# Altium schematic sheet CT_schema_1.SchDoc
size 516 x 258 mm
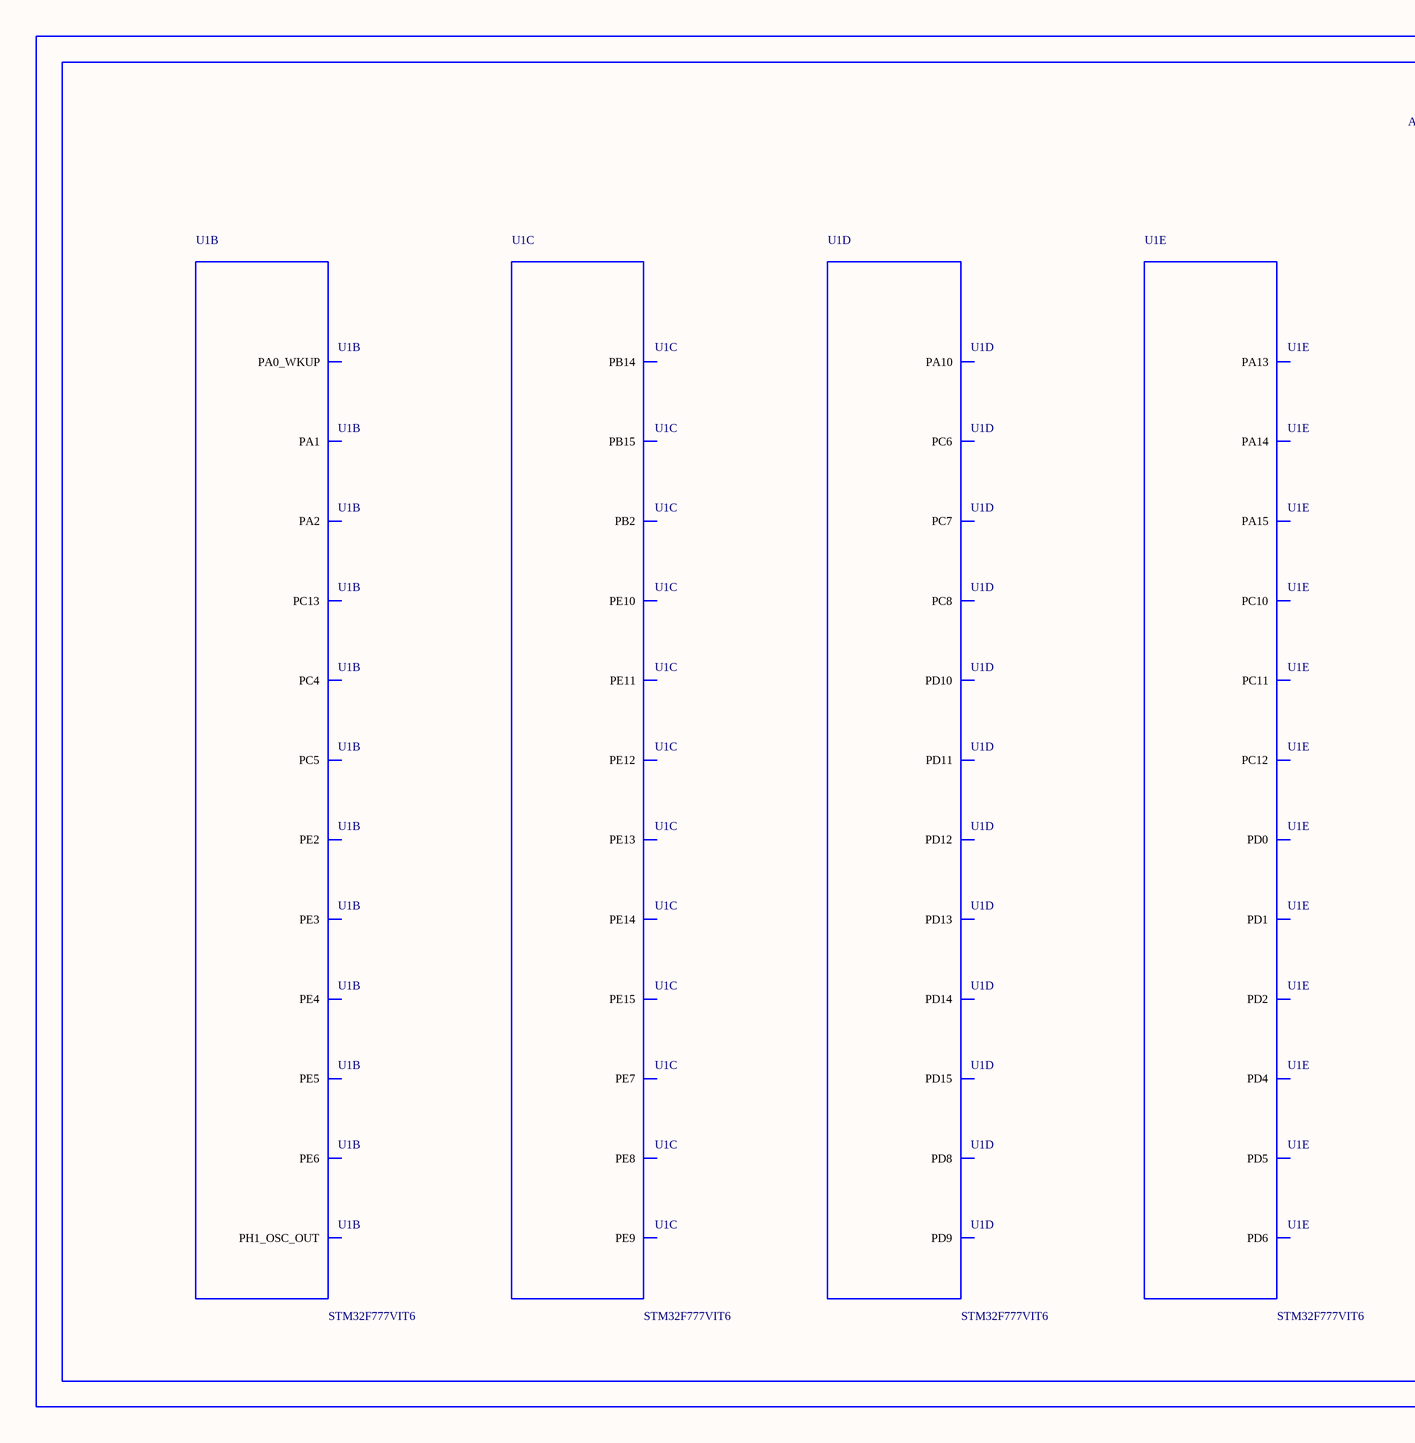
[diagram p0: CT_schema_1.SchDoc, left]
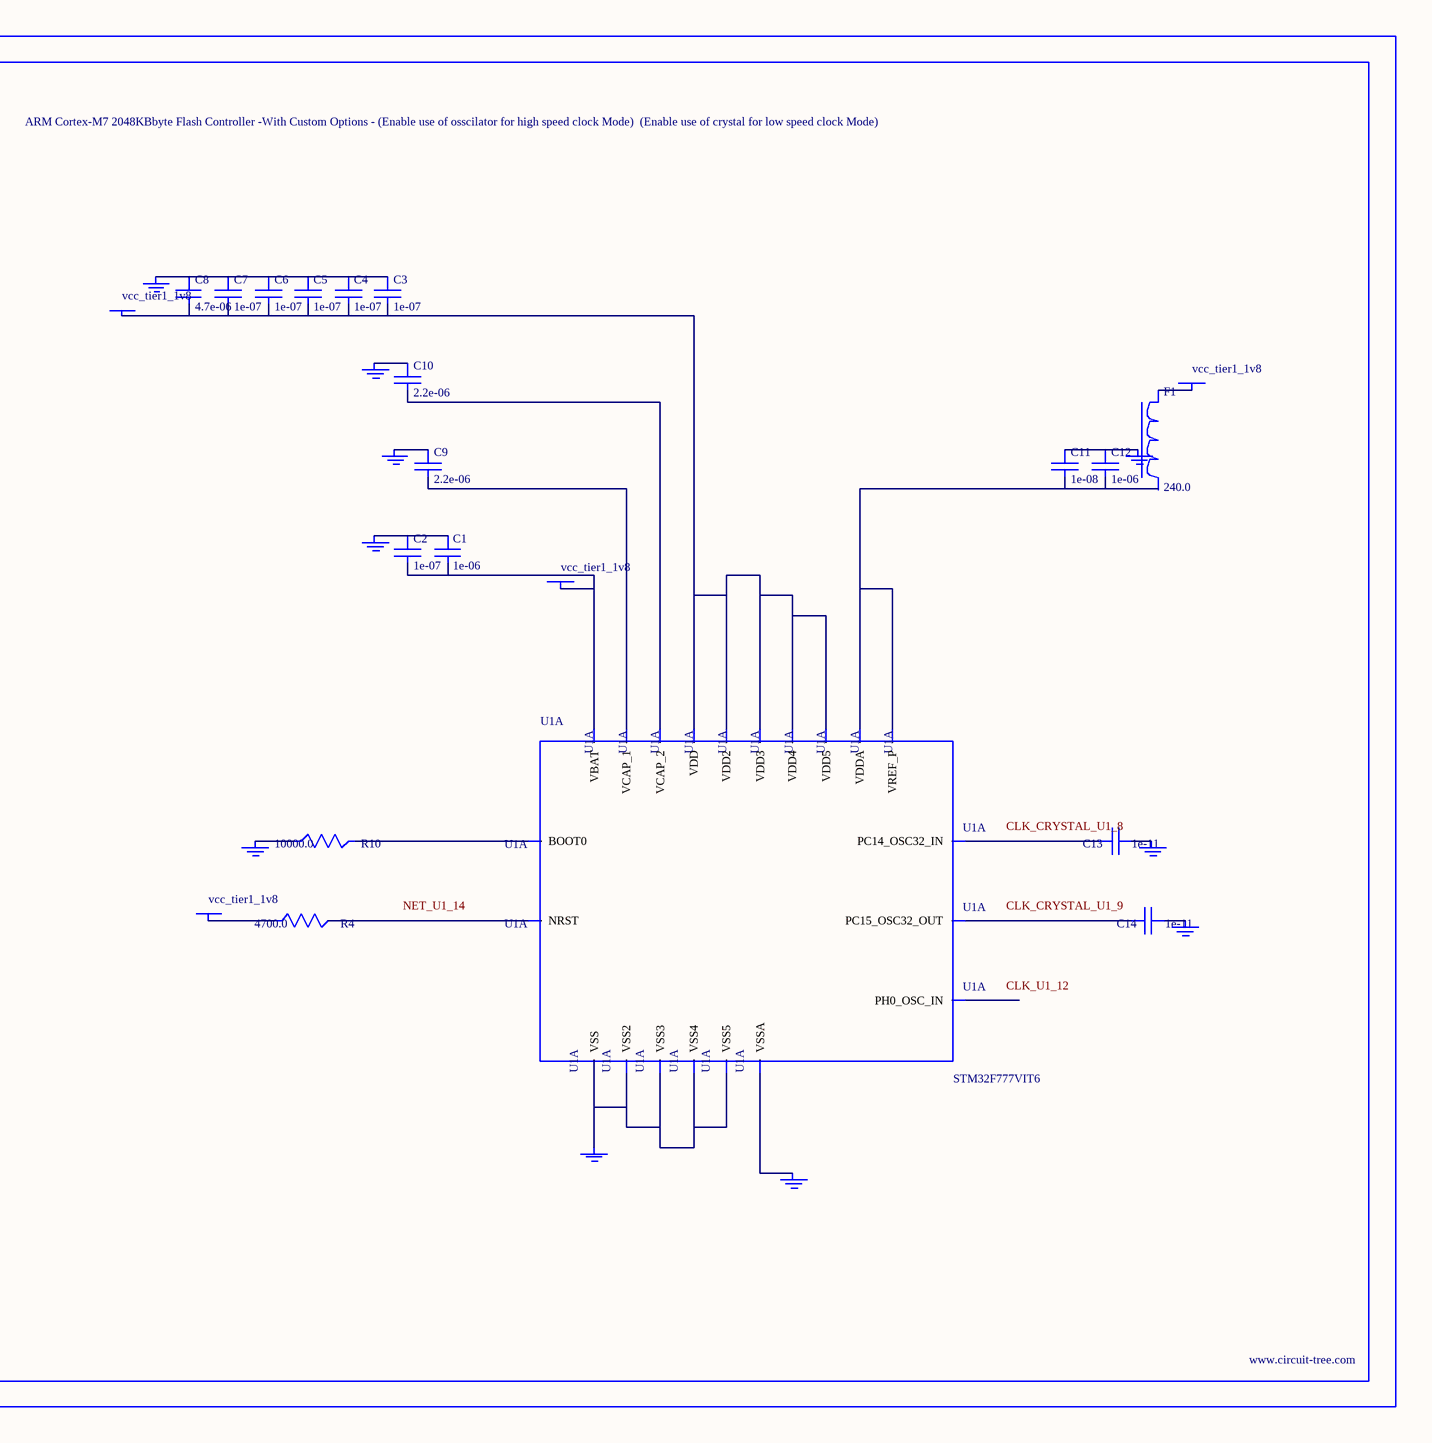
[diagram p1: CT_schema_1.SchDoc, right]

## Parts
BORDER0  (no value)
C1  1e-06  [C0603]
C2  1e-07  [C0603]
C3  1e-07  [C0603]
C4  1e-07  [C0603]
C5  1e-07  [C0603]
C6  1e-07  [C0603]
C7  1e-07  [C0603]
C8  4.7e-06  [C0603]
C9  2.2e-06  [C0603]
C10  2.2e-06  [C0603]
C11  1e-08  [C0603]
C12  1e-06  [C0603]
C13  1e-11  [C0402]
C14  1e-11  [C0402]
F1  240.0  [L0603]
GND_INSTANCE_0_0  (no value)
GND_INSTANCE_0_1  (no value)
GND_INSTANCE_0_2  (no value)
GND_INSTANCE_0_3  (no value)
GND_INSTANCE_0_4  (no value)
GND_INSTANCE_0_5  (no value)
GND_INSTANCE_0_6  (no value)
GND_INSTANCE_0_7  (no value)
GND_INSTANCE_0_8  (no value)
GND_INSTANCE_0_9  (no value)
POWER_INSTANCE_0_0  vcc_tier1_1v8
POWER_INSTANCE_0_1  vcc_tier1_1v8
POWER_INSTANCE_0_2  vcc_tier1_1v8
POWER_INSTANCE_0_3  vcc_tier1_1v8
R4  4700.0  [R0603]
R10  10000.0  [R0603]
U1  STM32F777VIT6  [LQFP100]  (parts A,B,C,D,E of 11)

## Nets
NetC1_1: C1.1 C2.1 GND_INSTANCE_0_0.0(GND)
NetC1_2: C1.2 C2.2 POWER_INSTANCE_0_0.0(PWR) U1.6(VBAT)
NetC3_1: C3.1 C4.1 C5.1 C6.1 C7.1 C8.1 GND_INSTANCE_0_3.0(GND)
NetC3_2: C3.2 C4.2 C5.2 C6.2 C7.2 C8.2 POWER_INSTANCE_0_1.0(PWR) U1.11(VDD) U1.27(VDD2) U1.50(VDD3) U1.75(VDD4) U1.100(VDD5)
NetC9_1: C9.1 GND_INSTANCE_0_6.0(GND)
NetC9_2: C9.2 U1.48(VCAP_1)
NetC10_1: C10.1 GND_INSTANCE_0_7.0(GND)
NetC10_2: C10.2 U1.73(VCAP_2)
NetC11_1: C11.1 C12.1 GND_INSTANCE_0_5.0(GND)
NetC11_2: C11.2 C12.2 U1.20(VREF_P) U1.21(VDDA)
NetC13_1: C13.1 GND_INSTANCE_0_1.0(GND)
NetC13_2: C13.2 U1.8(PC14_OSC32_IN)
NetC14_1: C14.1 GND_INSTANCE_0_2.0(GND)
NetC14_2: C14.2 U1.9(PC15_OSC32_OUT)
NetF1_1: F1.1 POWER_INSTANCE_0_2.0(PWR)
NetGND_INSTANCE_0_4_0: GND_INSTANCE_0_4.0(GND) U1.19(VSSA)
NetGND_INSTANCE_0_8_0: GND_INSTANCE_0_8.0(GND) R10.1
NetGND_INSTANCE_0_9_0: GND_INSTANCE_0_9.0(GND) U1.10(VSS) U1.26(VSS2) U1.49(VSS3) U1.74(VSS4) U1.99(VSS5)
NetPOWER_INSTANCE_0_3_0: POWER_INSTANCE_0_3.0(PWR) R4.1
NetR4_2: R4.2 U1.14(NRST)
NetR10_2: R10.2 U1.94(BOOT0)

Not connected (* = marked no-connect by the designer): F1 2; U1 1(PE2) 2(PE3) 3(PE4) 4(PE5) 5(PE6) 7(PC13) 12(PH0_OSC_IN) 13(PH1_OSC_OUT) 22(PA0_WKUP) 23(PA1) 24(PA2) 32(PC4) 33(PC5) 36(PB2) 37(PE7) 38(PE8) 39(PE9) 40(PE10) 41(PE11) 42(PE12) 43(PE13) 44(PE14) 45(PE15) 53(PB14) 54(PB15) 55(PD8) 56(PD9) 57(PD10) 58(PD11) 59(PD12) 60(PD13) 61(PD14) 62(PD15) 63(PC6) 64(PC7) 65(PC8) 69(PA10) 72(PA13) 76(PA14) 77(PA15) 78(PC10) 79(PC11) 80(PC12) 81(PD0) 82(PD1) 83(PD2) 85(PD4) 86(PD5) 87(PD6)

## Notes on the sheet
- Labels drawn without touching a wire or pin: CLK_CRYSTAL_U1_8, CLK_CRYSTAL_U1_9, CLK_U1_12, NET_U1_14

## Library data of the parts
BORDER0 = BORDER_PAGE0
C1 C12 = C0603C105K3RACTU
C2-C7 = 06035C104K4Z2A
C8 = GRM188R6YA475KE15D
C9 C10 = C0603C225K8RACTU
C11 = 06035C103K4Z2A
C13 C14 = C0402C100K3GACTU
F1 = Z0603C241ASMST
GND_INSTANCE_0_0-GND_INSTANCE_0_9 = GND
POWER_INSTANCE_0_0-POWER_INSTANCE_0_3 = PWR
R4 = RC0603JR-074K7L
R10 = RC0603JR-0710KL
